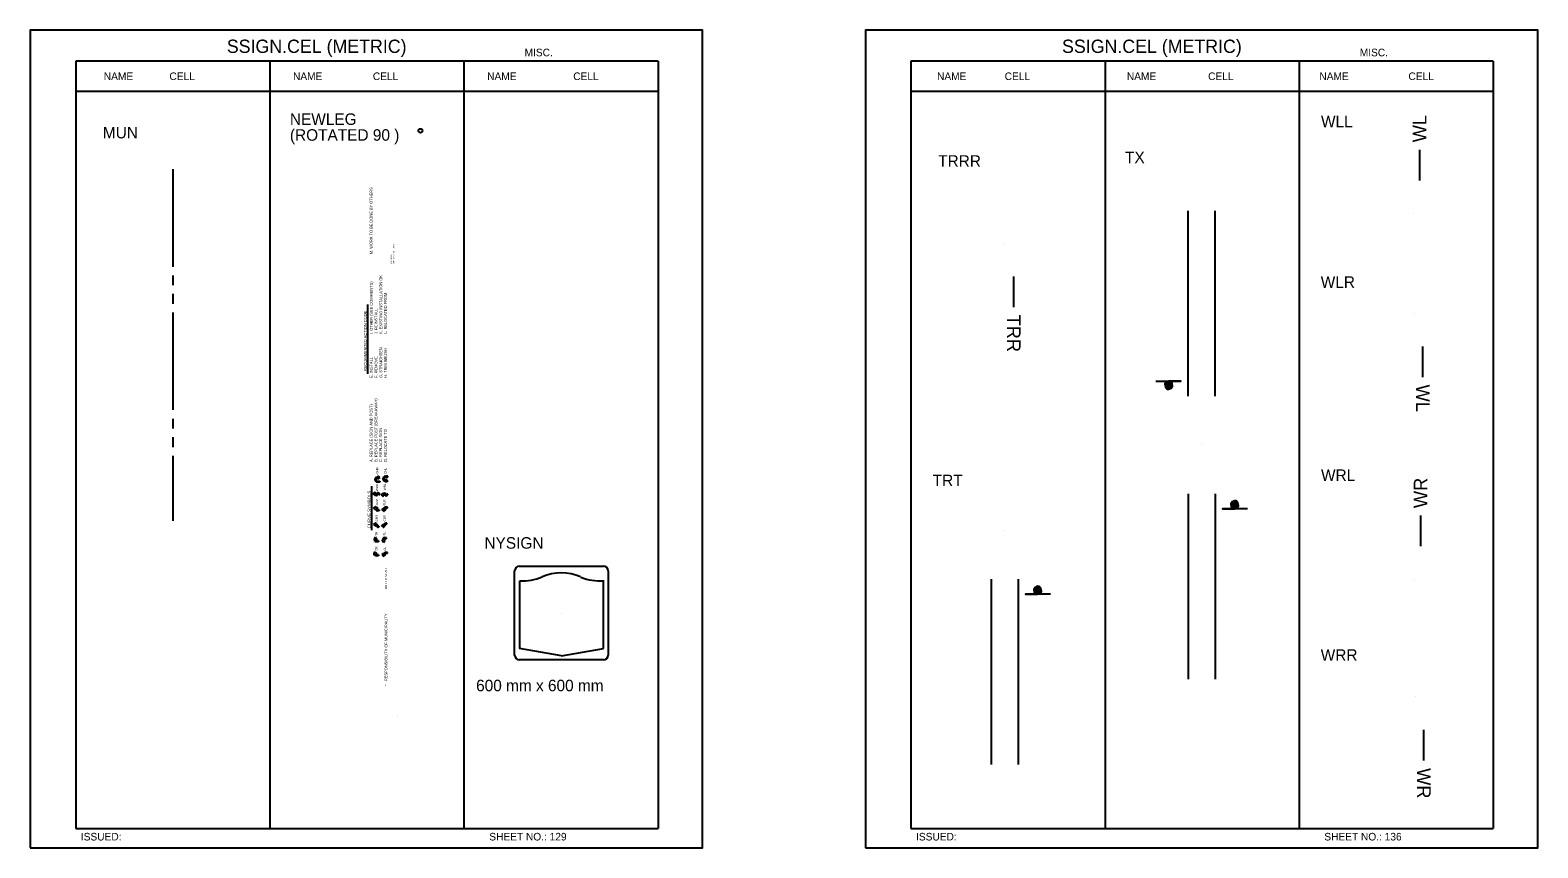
# Model space of a CAD drawing. Extents: x -12 to 6962, y -3756 to 679.
# Drawn here: x 673.1 to 1066, y -2779.8 to -2566.7 of the extents above; entities that cross this region are included whole.
import ezdxf

# ---------------------------------------------------------------- set-up
doc = ezdxf.new("R2010")
doc.units = 0
for name, color, linetype in [('Level 1', 7, 'Continuous'), ('Level 2', 7, 'Continuous'), ('Level 3', 7, 'Continuous'), ('Level 60', 7, 'Continuous')]:
    doc.layers.add(name, color=color, linetype=linetype)

msp = doc.modelspace()

# ---------------------------------------------------------------- linework, layer by layer
at = {"layer": 'Level 1'}
for p, q in [((836.73, -2574.77), (684.97, -2574.77)), ((684.97, -2574.77), (684.97, -2774.77)), ((735.56, -2574.77), (735.56, -2774.77)), ((735.56, -2574.77), (735.56, -2774.77)), ((786.14, -2574.77), (786.14, -2774.77)), ((786.14, -2574.77), (786.14, -2774.77)), ((836.73, -2574.77), (836.73, -2774.77)), ((1054.39, -2574.77), (902.64, -2574.77)), ((902.64, -2574.77), (902.64, -2774.77)), ((953.22, -2574.77), (953.22, -2774.77)), ((1003.81, -2574.77), (1003.81, -2774.77)), ((1054.39, -2574.77), (1054.39, -2774.77)), ((836.73, -2582.69), (684.97, -2582.69)), ((1054.39, -2582.69), (902.64, -2582.69)), ((1035.27, -2605.88), (1035.27, -2597.91)), ((710.3, -2602.97), (710.3, -2628.37)), ((974.86, -2662.14), (974.86, -2613.85)), ((981.97, -2662.14), (981.97, -2613.85)), ((1033.49, -2614.5), (1033.49, -2614.5)), ((927.14, -2622.3), (927.14, -2622.3)), ((710.3, -2630.66), (710.3, -2633.2)), ((929.36, -2630.92), (929.36, -2638.89)), ((710.3, -2635.48), (710.3, -2638.02)), ((710.3, -2640.31), (710.3, -2665.71)), ((761.08, -2656.32), (761.08, -2638.25)), ((1033.75, -2640.53), (1033.75, -2640.53)), ((710.3, -2647.42), (710.3, -2647.42)), ((1035.97, -2649.14), (1035.97, -2657.12)), ((710.3, -2667.99), (710.3, -2670.53)), ((710.3, -2672.82), (710.3, -2675.36)), ((978.41, -2674.83), (978.41, -2674.83)), ((978.41, -2674.83), (978.41, -2674.83)), ((710.3, -2677.64), (710.3, -2694.62)), ((763.58, -2683.22), (763.73, -2683.22)), ((763.58, -2683.43), (763.73, -2683.43)), ((763.73, -2683.22), (763.68, -2683.07)), ((763.73, -2683.43), (763.68, -2683.57)), ((764.19, -2683.32), (763.75, -2683.02)), ((764.19, -2683.32), (763.75, -2683.63)), ((766.28, -2682.99), (765.66, -2682.99)), ((765.66, -2683.21), (766.28, -2683.21)), ((766.28, -2683.21), (766.28, -2682.99)), ((766.28, -2683.13), (766.28, -2683.13)), ((762.16, -2697.07), (762.16, -2685.6)), ((762.42, -2687.55), (762.91, -2687.22)), ((762.42, -2687.55), (762.91, -2687.89)), ((762.94, -2687.44), (762.99, -2687.28)), ((762.94, -2687.44), (762.98, -2687.44)), ((763.46, -2687.52), (763.41, -2687.7)), ((763.58, -2684.27), (764.19, -2684.27)), ((764.19, -2684.49), (763.58, -2684.49)), ((763.69, -2687.59), (763.64, -2687.77)), ((764.21, -2687.53), (764.09, -2687.53)), ((764.19, -2684.27), (764.19, -2684.49)), ((764.19, -2684.35), (764.19, -2684.35)), ((764.21, -2687.53), (764.21, -2687.77)), ((764.54, -2687.83), (765.03, -2687.49)), ((765.06, -2687.71), (765.11, -2687.55)), ((765.66, -2684.05), (765.81, -2684.05)), ((765.66, -2684.26), (765.81, -2684.26)), ((765.81, -2687.79), (765.76, -2687.61)), ((765.81, -2684.05), (765.77, -2683.9)), ((765.81, -2684.26), (765.77, -2684.4)), ((766.28, -2684.15), (765.84, -2683.85)), ((766.28, -2684.15), (765.84, -2684.46)), ((766.33, -2687.61), (766.21, -2687.61)), ((766.33, -2687.85), (766.33, -2687.61)), ((974.86, -2687.53), (974.86, -2735.82)), ((981.97, -2687.53), (981.97, -2735.82)), ((762.61, -2691.33), (763.14, -2690.96)), ((762.61, -2691.33), (763.14, -2691.69)), ((762.94, -2687.67), (762.98, -2687.67)), ((762.94, -2687.67), (762.99, -2687.83)), ((763.17, -2691.2), (763.22, -2691.03)), ((763.17, -2691.2), (763.47, -2691.2)), ((763.17, -2691.45), (763.33, -2691.45)), ((763.17, -2691.45), (763.22, -2691.62)), ((763.39, -2691.84), (763.39, -2691.51)), ((763.65, -2691.7), (763.65, -2691.37)), ((764.09, -2687.77), (764.21, -2687.77)), ((764.54, -2687.83), (765.03, -2688.16)), ((764.74, -2691.7), (765.27, -2691.33)), ((765.06, -2687.71), (765.1, -2687.71)), ((765.06, -2687.95), (765.1, -2687.95)), ((765.06, -2687.95), (765.11, -2688.1)), ((765.3, -2691.57), (765.35, -2691.4)), ((765.52, -2691.19), (765.52, -2691.51)), ((765.58, -2687.86), (765.53, -2687.68)), ((766.21, -2691.01), (765.7, -2691.01)), ((765.78, -2691.33), (765.78, -2691.65)), ((766.21, -2691.27), (765.84, -2691.27)), ((766.33, -2687.85), (766.21, -2687.85)), ((766.21, -2691.27), (766.21, -2691.01)), ((762.57, -2695.56), (763.09, -2695.2)), ((763.12, -2695.43), (763.18, -2695.26)), ((763.12, -2695.43), (763.14, -2695.43)), ((764.08, -2692.01), (763.56, -2692.01)), ((764.08, -2691.75), (763.7, -2691.75)), ((764.08, -2691.75), (764.08, -2692.01)), ((764.74, -2691.7), (765.27, -2692.06)), ((765.3, -2691.57), (765.46, -2691.57)), ((765.3, -2691.82), (765.6, -2691.82)), ((765.3, -2691.82), (765.35, -2691.99)), ((765.56, -2695.39), (765.31, -2695.75)), ((766.08, -2695.24), (765.86, -2695.24)), ((766.08, -2695.5), (766.08, -2695.24)), ((1035.53, -2701.22), (1035.53, -2693.25)), ((762.57, -2695.56), (763.09, -2695.92)), ((763.08, -2698.85), (762.72, -2699.37)), ((762.95, -2699.41), (762.78, -2699.46)), ((762.95, -2699.86), (762.95, -2699.41)), ((763.08, -2698.85), (763.44, -2699.37)), ((763.12, -2695.69), (763.18, -2695.86)), ((763.12, -2695.69), (763.14, -2695.69)), ((763.21, -2699.72), (763.21, -2699.41)), ((763.21, -2699.41), (763.38, -2699.46)), ((763.49, -2696.09), (763.23, -2695.74)), ((763.69, -2695.94), (763.44, -2695.58)), ((764, -2695.99), (763.78, -2695.99)), ((764, -2696.24), (763.79, -2696.24)), ((764, -2695.99), (764, -2696.24)), ((764.64, -2695.92), (765.17, -2695.56)), ((764.64, -2695.92), (765.17, -2696.29)), ((765.05, -2699.23), (765.05, -2699.68)), ((765.2, -2695.8), (765.25, -2695.63)), ((765.2, -2695.8), (765.22, -2695.8)), ((765.2, -2696.05), (765.25, -2696.22)), ((765.2, -2696.05), (765.21, -2696.05)), ((765.99, -2699.05), (765.22, -2699.05)), ((765.31, -2699.37), (765.31, -2699.68)), ((765.99, -2699.31), (765.37, -2699.31)), ((765.77, -2695.54), (765.51, -2695.9)), ((766.08, -2695.5), (765.86, -2695.5)), ((765.99, -2699.31), (765.99, -2699.05)), ((927.07, -2697.11), (927.07, -2697.11)), ((762.75, -2702.7), (762.64, -2703.33)), ((762.87, -2703.26), (762.74, -2703.38)), ((762.75, -2702.7), (763.3, -2703.02)), ((762.87, -2703.26), (762.91, -2703.35)), ((763.1, -2703.15), (763.28, -2703.12)), ((763.1, -2703.15), (763.15, -2703.24)), ((763.89, -2700.04), (763.13, -2700.04)), ((763.89, -2699.78), (763.27, -2699.78)), ((763.89, -2699.78), (763.89, -2700.04)), ((765.18, -2700.24), (764.81, -2699.71)), ((765.05, -2699.68), (764.88, -2699.63)), ((765.06, -2703.87), (764.95, -2703.24)), ((765.17, -2703.31), (765.04, -2703.19)), ((765.17, -2703.31), (765.22, -2703.22)), ((765.18, -2700.24), (765.54, -2699.71)), ((765.31, -2699.68), (765.48, -2699.63)), ((765.41, -2703.42), (765.45, -2703.33)), ((766.19, -2702.88), (765.75, -2702.88)), ((766.19, -2703.14), (765.75, -2703.14)), ((766.19, -2703.14), (766.19, -2702.88)), ((763.88, -2703.43), (763.45, -2703.43)), ((763.88, -2703.69), (763.45, -2703.69)), ((763.88, -2703.43), (763.88, -2703.69)), ((765.06, -2703.87), (765.61, -2703.55)), ((765.41, -2703.42), (765.59, -2703.45)), ((800.6, -2710.2), (800.6, -2727.9)), ((822.49, -2727.9), (822.49, -2710.08)), ((923.51, -2709.81), (923.51, -2758.1)), ((930.62, -2709.81), (930.62, -2758.1)), ((1033.75, -2709.84), (1033.75, -2709.84)), ((811.55, -2718.64), (811.55, -2718.64)), ((811.55, -2718.64), (811.55, -2718.64)), ((811.55, -2729.81), (800.61, -2727.88)), ((811.56, -2729.8), (822.49, -2727.88)), ((1034.01, -2740.49), (1034.01, -2740.49)), ((768.72, -2745.57), (768.72, -2745.57)), ((1036.23, -2749.1), (1036.23, -2757.08)), ((684.97, -2774.77), (836.73, -2774.77)), ((902.64, -2774.77), (1054.39, -2774.77))]:
    msp.add_line(p, q, dxfattribs=at)
for centre, radius, start, end in [((763.58, -2683.85), 0.635, 90.0348, 269.9652), ((763.58, -2683.85), 0.419, 90.0348, 269.9652), ((763.73, -2683.06), 0.0478, 58.3416, 196.1912), ((763.73, -2683.59), 0.0478, 163.8088, 301.6584), ((765.66, -2683.63), 0.635, 90.0348, 269.9652), ((765.66, -2683.63), 0.419, 90.0348, 269.9652), ((762.94, -2687.26), 0.0528, 343.2859, 121.9034), ((762.98, -2687.74), 0.304, 8.644, 90.2112), ((763.75, -2687.61), 0.304, 23.6029, 163.7917), ((763.75, -2687.61), 0.0645, 23.4869, 163.5024), ((764.09, -2687.46), 0.304, 203.4985, 270.0015), ((764.09, -2687.46), 0.0654, 202.2564, 268.7266), ((765.06, -2687.53), 0.0528, 343.2859, 121.9034), ((765.47, -2687.69), 0.304, 16.2307, 171.5985), ((765.47, -2687.7), 0.0649, 16.4427, 171.9068), ((765.81, -2683.89), 0.0478, 58.3416, 196.1912), ((765.81, -2684.42), 0.0478, 163.8088, 301.6584), ((766.21, -2687.92), 0.304, 89.9985, 156.5015), ((762.94, -2687.85), 0.0528, 238.0966, 16.7141), ((762.98, -2687.74), 0.0642, 7.8954, 90.0864), ((763.35, -2687.69), 0.304, 188.4015, 343.7693), ((763.17, -2691.01), 0.0572, 343.8259, 121.6413), ((763.35, -2687.68), 0.0649, 188.0932, 343.5573), ((763.33, -2691.51), 0.0589, 0, 90), ((763.47, -2691.37), 0.177, 0, 90), ((765.06, -2688.12), 0.0528, 238.0966, 16.7141), ((765.1, -2687.64), 0.0642, 269.9136, 352.1046), ((765.1, -2687.64), 0.304, 269.7888, 351.356), ((765.3, -2691.38), 0.0572, 343.7978, 121.6694), ((765.46, -2691.51), 0.0589, 270, 360), ((765.69, -2691.19), 0.177, 90, 180), ((765.87, -2687.77), 0.304, 196.2083, 336.3971), ((765.84, -2691.33), 0.0591, 90, 180), ((765.87, -2687.77), 0.0645, 196.4976, 336.5131), ((766.21, -2687.92), 0.0654, 91.2734, 157.7436), ((763.12, -2695.25), 0.0572, 343.8088, 121.6584), ((763.17, -2691.64), 0.0572, 238.3306, 16.2022), ((763.14, -2695.8), 0.369, 35.7541, 90.1328), ((763.56, -2691.83), 0.177, 180, 270), ((763.71, -2691.69), 0.0591, 180, 270), ((765.3, -2692.01), 0.0572, 238.3587, 16.1741), ((765.86, -2695.61), 0.369, 89.8672, 144.2459), ((765.6, -2691.65), 0.177, 270, 0), ((762.77, -2699.4), 0.0572, 148.3416, 286.1912), ((763.12, -2695.88), 0.0572, 238.3587, 16.1741), ((763.14, -2695.8), 0.111, 35.7926, 89.6684), ((763.4, -2699.4), 0.0572, 253.8088, 31.6584), ((763.78, -2695.88), 0.369, 215.7541, 270.1328), ((763.78, -2695.88), 0.11, 215.4525, 270.0086), ((765.22, -2699.23), 0.177, 90, 180), ((765.2, -2695.61), 0.0572, 343.8259, 121.6413), ((765.2, -2696.24), 0.0572, 238.3416, 16.1912), ((765.22, -2695.68), 0.369, 269.8672, 324.2459), ((765.22, -2695.68), 0.111, 270.3316, 324.2074), ((765.36, -2699.37), 0.059, 90, 180), ((765.86, -2695.61), 0.11, 89.9914, 144.5475), ((762.7, -2703.33), 0.057, 172.8825, 311.323), ((763.45, -2703.1), 0.591, 204.6696, 270.0193), ((763.13, -2699.86), 0.177, 180, 270), ((763.45, -2703.1), 0.333, 205.2638, 269.9076), ((763.27, -2699.72), 0.059, 180, 270), ((763.27, -2703.07), 0.0571, 278.2383, 56.8115), ((764.86, -2699.68), 0.0572, 73.8088, 211.6584), ((765.01, -2703.24), 0.057, 48.677, 187.1175), ((765.75, -2703.47), 0.591, 89.9807, 155.3304), ((765.75, -2703.47), 0.333, 90.0924, 154.7362), ((765.49, -2699.68), 0.0572, 328.3416, 106.1912), ((765.58, -2703.5), 0.0571, 303.1885, 81.7617), ((801.45, -2697.65), 12.59, 266.7291, 293.6309), ((811.48, -2720.74), 12.59, 66.2313, 113.3149), ((821.45, -2697.65), 12.59, 247.5444, 274.8093)]:
    msp.add_arc(centre, radius, start, end, dxfattribs=at)
at = {"layer": 'Level 2'}
for points in [[(966.5, -2658.2), (973.02, -2658.2), (969.86, -2658.2), (969.19, -2658.43), (968.84, -2658.94), (968.96, -2659.72), (969.39, -2660.26), (969.78, -2660.3), (970.44, -2659.99), (970.79, -2659.48), (970.75, -2658.74), (970.32, -2658.31), (969.62, -2658.43), (969.12, -2659.05), (969.27, -2659.56), (969.58, -2659.91), (970.25, -2659.72), (970.52, -2659.09), (970.13, -2658.74), (969.62, -2658.74), (969.43, -2659.05), (969.47, -2659.44), (969.82, -2659.48), (970.01, -2659.25), (970.01, -2659.02), (969.78, -2658.94), (969.74, -2659.17)], [(990.32, -2691.47), (983.81, -2691.47), (986.97, -2691.47), (987.63, -2691.24), (987.98, -2690.73), (987.86, -2689.95), (987.44, -2689.4), (987.05, -2689.36), (986.38, -2689.68), (986.03, -2690.18), (986.07, -2690.92), (986.5, -2691.35), (987.2, -2691.24), (987.71, -2690.61), (987.55, -2690.1), (987.24, -2689.75), (986.58, -2689.95), (986.3, -2690.57), (986.69, -2690.92), (987.2, -2690.92), (987.4, -2690.61), (987.36, -2690.22), (987.01, -2690.18), (986.81, -2690.42), (986.81, -2690.65), (987.05, -2690.73), (987.08, -2690.49)], [(938.98, -2713.75), (932.46, -2713.75), (935.62, -2713.75), (936.29, -2713.52), (936.64, -2713.01), (936.52, -2712.23), (936.09, -2711.68), (935.7, -2711.64), (935.04, -2711.96), (934.69, -2712.46), (934.73, -2713.2), (935.15, -2713.63), (935.86, -2713.52), (936.36, -2712.89), (936.21, -2712.38), (935.9, -2712.03), (935.23, -2712.23), (934.96, -2712.85), (935.35, -2713.2), (935.86, -2713.2), (936.05, -2712.89), (936.01, -2712.5), (935.66, -2712.46), (935.47, -2712.7), (935.47, -2712.93), (935.7, -2713.01), (935.74, -2712.78)]]:
    msp.add_lwpolyline(points, dxfattribs=at)
at = {"layer": 'Level 3'}
for p, q in [((800.58, -2706.44), (822.52, -2706.44)), ((799.36, -2729.61), (799.36, -2707.66)), ((823.74, -2707.66), (823.74, -2729.61)), ((822.52, -2730.83), (800.58, -2730.83))]:
    msp.add_line(p, q, dxfattribs=at)
msp.add_circle((774.8, -2592.93), 0.515, dxfattribs=at)
for centre, start, end in [((800.58, -2707.66), 90, 180), ((822.52, -2707.66), 0, 90), ((800.58, -2729.61), 180, 270), ((822.52, -2729.61), 270, 0)]:
    msp.add_arc(centre, 1.22, start, end, dxfattribs=at)
at = {"layer": 'Level 60'}
for points in [[(673.09, -2779.82), (848.36, -2779.82), (848.36, -2566.73), (673.09, -2566.73)], [(890.76, -2779.82), (1066.02, -2779.82), (1066.02, -2566.73), (890.76, -2566.73)]]:
    msp.add_lwpolyline(points, close=True, dxfattribs=at)

# ---------------------------------------------------------------- texts
at = {"layer": 'Level 1'}
for s, height, rotation, p in [('WL', 3.556, 90, (1036.97, -2595.95)), ('M. WORK TO BE DONE BY OTHERS', 0.7425, 90, (762.33, -2625.12)), ('WORK ORDER NO.          ', 0.4125, 90, (768.04, -2627.59)), ('REVISED:        ', 0.4125, 90, (767.42, -2627.59)), ('K. EXISTING INSTALLATION OK', 0.7425, 90, (764.84, -2645.91)), ('I. OTHER (SEE COMMENTS)', 0.7425, 90, (762.37, -2645.93)), ('L. RELOCATED FROM', 0.7425, 90, (766.07, -2645.86)), ('RECOMMENDED ACTION CODE', 0.7425, 90, (760.81, -2655.55)), ('J. REINSTALL', 0.7425, 90, (763.61, -2645.91)), ('TRR', 3.556, 270, (927.66, -2640.85)), ('E. INSTALL', 0.743, 90, (762.36, -2657.34)), ('F. REMOVE', 0.743, 90, (763.61, -2657.36)), ('G. STRAIGHTEN', 0.7425, 90, (764.84, -2657.36)), ('H. TRIM BRUSH', 0.7425, 90, (766.07, -2657.34)), ('WL', 3.556, 270, (1034.27, -2659.08)), ('B. REPLACE POST (BREAKAWAY)', 0.7425, 90, (763.59, -2679.26)), ('A. REPLACE (SIGN AND POST) ', 0.7425, 90, (762.34, -2679.25)), ('C. REPLACE SIGN', 0.7425, 90, (764.82, -2679.26)), ('D. RELOCATE TO', 0.7425, 90, (766.07, -2679.26)), ('-CHR', 0.577, 90, (763.82, -2682.66)), ('-CHL', 0.577, 90, (765.98, -2682.63)), ('WR', 3.556, 90, (1037.23, -2691.29)), ('CURVE SYMBOLS', 0.825, 90, (761.88, -2696.56)), ('-WRR', 0.577, 90, (763.78, -2687.14)), ('WRL', 0.577, 90, (765.82, -2686.63)), ('-', 0.577, 90, (765.79, -2687.28)), ('-TRR', 0.577, 90, (763.78, -2690.85)), ('-TLR', 0.577, 90, (765.72, -2690.83)), ('-CRR', 0.577, 90, (763.73, -2695.03)), ('-CLR', 0.577, 90, (765.72, -2695.03)), ('-TR', 0.577, 90, (763.65, -2698.77)), ('-TL', 0.577, 90, (765.75, -2698.68)), ('-CR', 0.577, 90, (763.62, -2702.72)), ('-CL', 0.577, 90, (765.83, -2702.68)), ('NOT TO SCALE', 0.5775, 90, (766.13, -2712.45)), ('RESPONSIBILITY OF MUNICIPALITY', 0.7425, 90, (766.21, -2736.35)), ('*', 0.743, 90, (766.24, -2737.68)), ('WR', 3.556, 270, (1034.53, -2759.04))]:
    msp.add_text(s, height=height, rotation=rotation, dxfattribs=at).set_placement(p)
at = {"layer": 'Level 3'}
for s, height, p in [('SSIGN.CEL (METRIC)', 3.4642, (724.35, -2572.66)), ('SSIGN.CEL (METRIC)', 3.4642, (942.02, -2572.66)), ('MISC.', 1.979, (801.95, -2573.54)), ('MISC.', 1.979, (801.95, -2573.54)), ('MISC.', 1.979, (1019.62, -2573.54)), ('NAME', 1.98, (692.29, -2579.73)), ('CELL', 1.98, (709.4, -2579.73)), ('NAME', 1.98, (741.6, -2579.73)), ('CELL', 1.98, (762.41, -2579.73)), ('NAME', 1.98, (792.2, -2579.73)), ('CELL', 1.98, (814.63, -2579.73)), ('NAME', 1.98, (909.45, -2579.73)), ('CELL', 1.98, (927.07, -2579.73)), ('NAME', 1.98, (958.92, -2579.73)), ('CELL', 1.98, (980.09, -2579.73)), ('NAME', 1.98, (1009.09, -2579.73)), ('CELL', 1.98, (1032.3, -2579.73)), ('NEWLEG', 3, (740.79, -2591.42)), ('WLL', 3, (1009.52, -2592.03)), ('MUN', 3, (692.04, -2594.93)), ('(ROTATED 90 )', 3, (740.79, -2595.54)), ('TRRR', 3, (909.74, -2602.32)), ('TX', 3, (958.44, -2601.4)), ('WLR', 3, (1009.44, -2633.88)), ('TRT', 3, (908.32, -2685.56)), ('WRL', 3, (1009.52, -2684.19)), ('NYSIGN', 3, (791.49, -2701.86)), ('WRR', 3, (1009.44, -2731.07)), ('600 mm x 600 mm', 3, (789.32, -2739.01)), ('ISSUED:', 1.98, (686.31, -2777.9)), ('SHEET NO.: 129', 1.9795, (792.75, -2777.9)), ('ISSUED:', 1.98, (903.98, -2777.9)), ('SHEET NO.: 136', 1.9795, (1010.37, -2777.9))]:
    msp.add_text(s, height=height, dxfattribs=at).set_placement(p)

doc.saveas('drawing.dxf')
